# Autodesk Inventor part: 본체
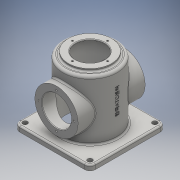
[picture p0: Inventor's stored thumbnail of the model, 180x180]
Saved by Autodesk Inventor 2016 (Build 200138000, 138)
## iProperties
Created: 2019-08
Part Number: 본체
Material: 일반
Document SubType Name: Modeling
Designer: user
Density: 1 g/cm^3
Appearance: 기본값
Author: user
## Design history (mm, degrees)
sketch "스케치1"
  geometry: L1 (-70, -70)-(70, -70); L2 (70, -70)-(70, 70); L3 (70, 70)-(-70, 70); L4 (-70, 70)-(-70, -70); L5 (-70, -70)-(70, 70); L6 (70, -70)-(-70, 70); 1 further point
  constraints: 12 end point, 2 midpoint, 2 parallel, 1 horizontal, 1 perpendicular
  dimensions: "d0" = 140 distance of L3.end L2.end; "d1" = 140 distance of L2.end L1.end
extrude "돌출1" new body sketch "스케치1" distance "d2" = 10; taper "d3" = 0 deg
sketch "스케치2"
  geometry: C1 r 50 at (0, 0); 1 further point
  constraints: 1 centre point, 1 coincident
  dimensions: "d4" = 100 diameter of C1
extrude "돌출2" join sketch "스케치2" distance "d5" = 110; taper "d6" = 0 deg
node "작업 평면1"
sketch "스케치3"
  geometry: L1 (70, 0)-(-70, 0) reference; C1 r 40 at (0, 60); 2 further points
  constraints: 1 centre point, 1 midpoint, 1 vertical alignment
  dimensions: "d8" = 80 diameter of C1; "d9" = 60 distance from line of L1 C1.centre
extrude "돌출3" join sketch "스케치3" stored distance "d10" = 110; taper "d11" = 0 deg
sketch "스케치4"
  geometry: C1 r 40 at (0, 0); 1 further point
  constraints: 1 centre point, 1 coincident
  dimensions: "d12" = 80 diameter of C1
extrude "돌출4" join sketch "스케치4" distance "d13" = 5; taper "d14" = 0 deg
hole "구멍1" diameter "d17" = 54; stored, may be unused: countersink angle "d21" = 90 deg, drill point angle "d23" = 118 deg; dims "d15" = 10, "d16" = 10, "d18" = 6, "d19" = 4, "d20" = 2, "d22" = 8
hole "구멍2" diameter "d26" = 90; stored, may be unused: countersink angle "d30" = 90 deg, drill point angle "d32" = 118 deg; dims "d24" = 10, "d25" = 10, "d27" = 6, "d28" = 4, "d29" = 2, "d31" = 112
hole "구멍3" diameter "d35" = 54; stored, may be unused: countersink angle "d39" = 90 deg, drill point angle "d41" = 118 deg; dims "d33" = 10, "d34" = 10, "d36" = 6, "d37" = 4, "d38" = 2, "d40" = 112
sketch "스케치5"
  geometry: L1 (70, -50)-(70, -60) reference; L2 (70, -60)-(-70, -60) reference; L3 (-70, -60)-(-70, -50) reference; L4 (-70, -50)-(70, -50) reference; C1 r 27 at (0, 0) reference; C2 r 40 at (0, 0) reference; 2 further points
  constraints: 1 vertical alignment
  dimensions: "d43" = 32.5 distance of C1.centre point (0, 32.5)
hole "구멍4" sketch "스케치5" at (0, 32.5) diameter "d44" = 3.242; stored, may be unused: countersink angle "d48" = 90 deg, drill point angle "d50" = 118 deg; dims "d45" = 8, "d46" = 4, "d47" = 2, "d49" = 10
sketch "스케치6"
  geometry: 2 further points
  constraints: 1 vertical alignment
  dimensions: "d54" = 32.5 distance of point (0, 0) point (0, -32.5)
hole "구멍5" sketch "스케치6" at (0, -32.5) diameter "d55" = 3.242; stored, may be unused: countersink angle "d59" = 90 deg, drill point angle "d61" = 118 deg; dims "d56" = 8, "d57" = 4, "d58" = 2, "d60" = 10
fillet "모깎기1" dims "d65" = 10
hole "구멍6" diameter "d68" = 9; stored, may be unused: countersink angle "d72" = 90 deg, drill point angle "d74" = 0 deg; dims "d66" = 10, "d67" = 10, "d69" = 8, "d70" = 4, "d71" = 2, "d73" = 10
fillet "모깎기2" dims "d81" = 3
fillet "모깎기3" dims "d82" = 3
fillet "모깎기4" dims "d83" = 3
fillet "모깎기5" dims "d84" = 3
fillet "모깎기6" dims "d85" = 3
fillet "모깎기7" dims "d86" = 5
chamfer "모따기1" distance "d87" = 1; stored, may be unused: second distance "d88" = 2, angle "d89" = 45 deg
chamfer "모따기2" distance "d90" = 1; stored, may be unused: second distance "d91" = 2, angle "d92" = 45 deg
fillet "모깎기8" dims "d93" = 3
node "작업 평면2"
sketch "스케치7" dims "d0" = 140, "d1" = 140
  geometry: L1 (-60, 0)-(60, 0) reference; 3 further points
  constraints: 1 midpoint, 1 vertical alignment, 1 other
  dimensions: "d95" = 70 distance from line of L1 point (0, 70)
feature "엠보싱1" sketch "스케치7" dims "d96" = 0.5, "d97" = 0
node "솔리드1"
mirror "대칭1"
pattern_circular "원형 패턴1" dims angle "d52" = 360 deg
mirror "대칭2"
pattern_circular "원형 패턴2" dims angle "d63" = 360 deg
pattern_linear "직사각형 패턴1" dims "d77" = 120
node "절단 모서리 투영1"
other parameters: "d7" = -62, "d94" = 55
